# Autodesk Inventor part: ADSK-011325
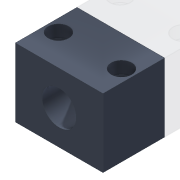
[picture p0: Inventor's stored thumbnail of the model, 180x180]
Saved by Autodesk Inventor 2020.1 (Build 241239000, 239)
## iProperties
Created: 1999-12
Part Number: ADSK-011325
Material: RA Nylatron
Description: PLT-03,SN,CP,17,025,020,999,BLOCK,SLIDER
Document SubType Name: Modeling
Designer: sspink
Density: 1.13867 g/cm^3
Appearance: Nylatron
Mass: 129.254 g
Surface Area: 221.248 cm^2
Volume: 113.513 cm^3
Control State: 0
Checked Out: False
Last Check In By: sspink
Last Check In Date: 1999-12-22
Master: False
Shininess: 10.0
Length Units: 11269
Angle Units: 11279
Time Units: 11290
Mass Units: 11283
Length Display Precision: 3
Angle Display Precision: 2
Compacted: True
Cutlength: 2..50 X 2.00 (5.00 SI)
Material Desc: SHEET,NYLATRON,1.750
Material_number: A096384
Dimensions: 64x50x45 mm
Mass: 0,129 kg
DocNumber: ADSK-011325.ipt
Folder: 01 - Themengebiete\Simplification\01 - Packaging machine\
VDS_Category: 3D Komponenten
Density: 1.13867
Volumn: 115.1096676409313
Area: 215.06074706719897
PropertySet Name: Model Information
Author: sspink
Revision Number: -
Title: distance
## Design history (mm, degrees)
node "Solide1"
  node "Extrusion1" dims "d2" = 45, "d3" = 0
  node "Extrusion2" dims "d5" = 44.45, "d6" = 0
  node "Hole1" dims "d9" = 9, "d10" = 15, "d11" = 9, "d12" = 60 deg, "d13" = 19.05, "d14" = 118 deg, "d15" = 6
sketch "Sketch1"
  geometry: L1 (0, 0)-(-64, 0) reference; L2 (-64, 0)-(-64, 50); L3 (-64, 50)-(0, 50); L4 (0, 50)-(0, 0) reference
  constraints: 8 end point, 2 horizontal, 2 parallel, 1 perpendicular, 1 vertical
  dimensions: "d0" = 50 distance of L1.end L2.end; "d1" = 64 distance of L2.end L3.end
sketch "Sketch2"
  geometry: L1 (0, 0)-(-64, 0) reference; L2 (0, 50)-(0, 0) reference; L3 (-64, 50)-(0, 50) reference; L4 (-64, 0)-(-64, 50) reference; L5 (-64, 25)-(0, 25); L6 (-32, 50)-(-32, 0); C1 r 12.5 at (-32, 25)
  constraints: 5 midpoint, 4 end point, 1 centre point
  dimensions: "d4" = 25 diameter of C1
sketch "Sketch3"
  geometry: L1 (0, 0)-(0, -45) reference; L2 (9, -22.5)-(55, -22.5); L3 (64, 0)-(0, 0) reference; 3 further points
  constraints: 3 midpoint, 2 end point, 1 horizontal, 1 horizontal alignment, 1 vertical alignment
  dimensions: "d16" = 46 distance of L2.start L2.end
node "Corps solides"
node "Corps surfaciques"
